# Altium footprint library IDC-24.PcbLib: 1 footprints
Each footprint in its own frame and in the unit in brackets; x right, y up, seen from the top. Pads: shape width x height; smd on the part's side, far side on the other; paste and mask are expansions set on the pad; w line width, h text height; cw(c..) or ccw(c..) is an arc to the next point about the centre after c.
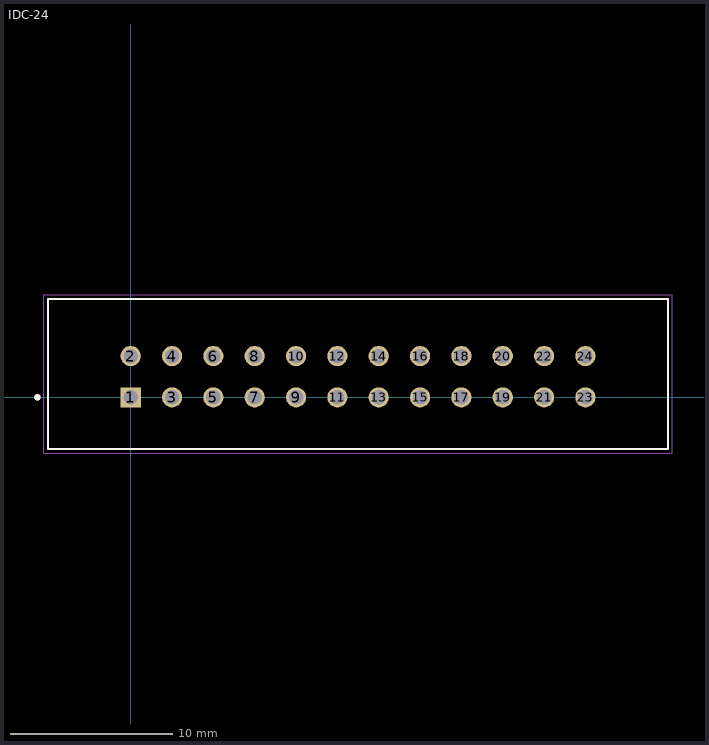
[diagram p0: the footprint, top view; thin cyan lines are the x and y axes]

## IDC-24 [mm]
pads (24):
  rect 1.24x1.24 hole 0.89: 1(0,0)
  round 1.24 hole 0.89: 2(0,2.54) 3(2.54,0) 4(2.54,2.54) 5(5.08,0) 6(5.08,2.54) 7(7.62,0) 8(7.62,2.54) 9(10.16,0) 10(10.16,2.54) 11(12.7,0) 12(12.7,2.54) 13(15.24,0) 14(15.24,2.54) 15(17.78,0) 16(17.78,2.54) 17(20.32,0) 18(20.32,2.54) 19(22.86,0) 20(22.86,2.54) 21(25.4,0) 22(25.4,2.54) 23(27.94,0) 24(27.94,2.54)
Top Overlay:
  circle w0.2: c-5.73,0 r0.1
  lines w0.127: -5.08,-3.175 33.02,-3.175 33.02,6.045 -5.08,6.045 -5.08,-3.175
Mechanical 13:
  circle w0.2: c-5.73,0 r0.1
  lines w0.127: -5.08,-3.175 -5.08,6.045 ; -5.08,-3.175 33.02,-3.175 ; -5.08,-3.175 -5.08,6.045 ; -5.08,6.045 33.02,6.045 ; -5.08,6.045 33.02,6.045 ; 33.02,-3.175 33.02,6.045 ; 33.02,-3.175 33.02,6.045
Mechanical 15:
  lines w0.05: -5.33,-3.425 33.27,-3.425 33.27,6.295 -5.33,6.295 -5.33,-3.425
3D body "IDC-24.STEP": height 8.99, standoff -2.82, extent -5.08,-3.175 33.02,6.045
